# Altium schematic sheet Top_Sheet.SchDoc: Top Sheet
size A4; ApprovedBy: Watzek; CheckedBy: Watzek; Author: Watzek; DrawnBy: Watzek; Organization: HTL Hollabrunn; Address1: Abteilung Elektronik; Address2: Anton Ehrenfried-Straße 10; Address3: 2020 Hollabrunn; DocumentNumber: 01; Revision: 01; SheetNumber: 01; SheetTotal: 02; SPICEModelCacheIHPBHSPQ: <root> / <DocumentId>IHPBHSPQ</DocumentId> / <CacheFrame Number="0"> / <Model Name="cap" Kind="MDL"> / <Text>*Default semiconductor capacitor / .MODEL CAP C()</Text> / </Model> / </CacheFrame> / </root>
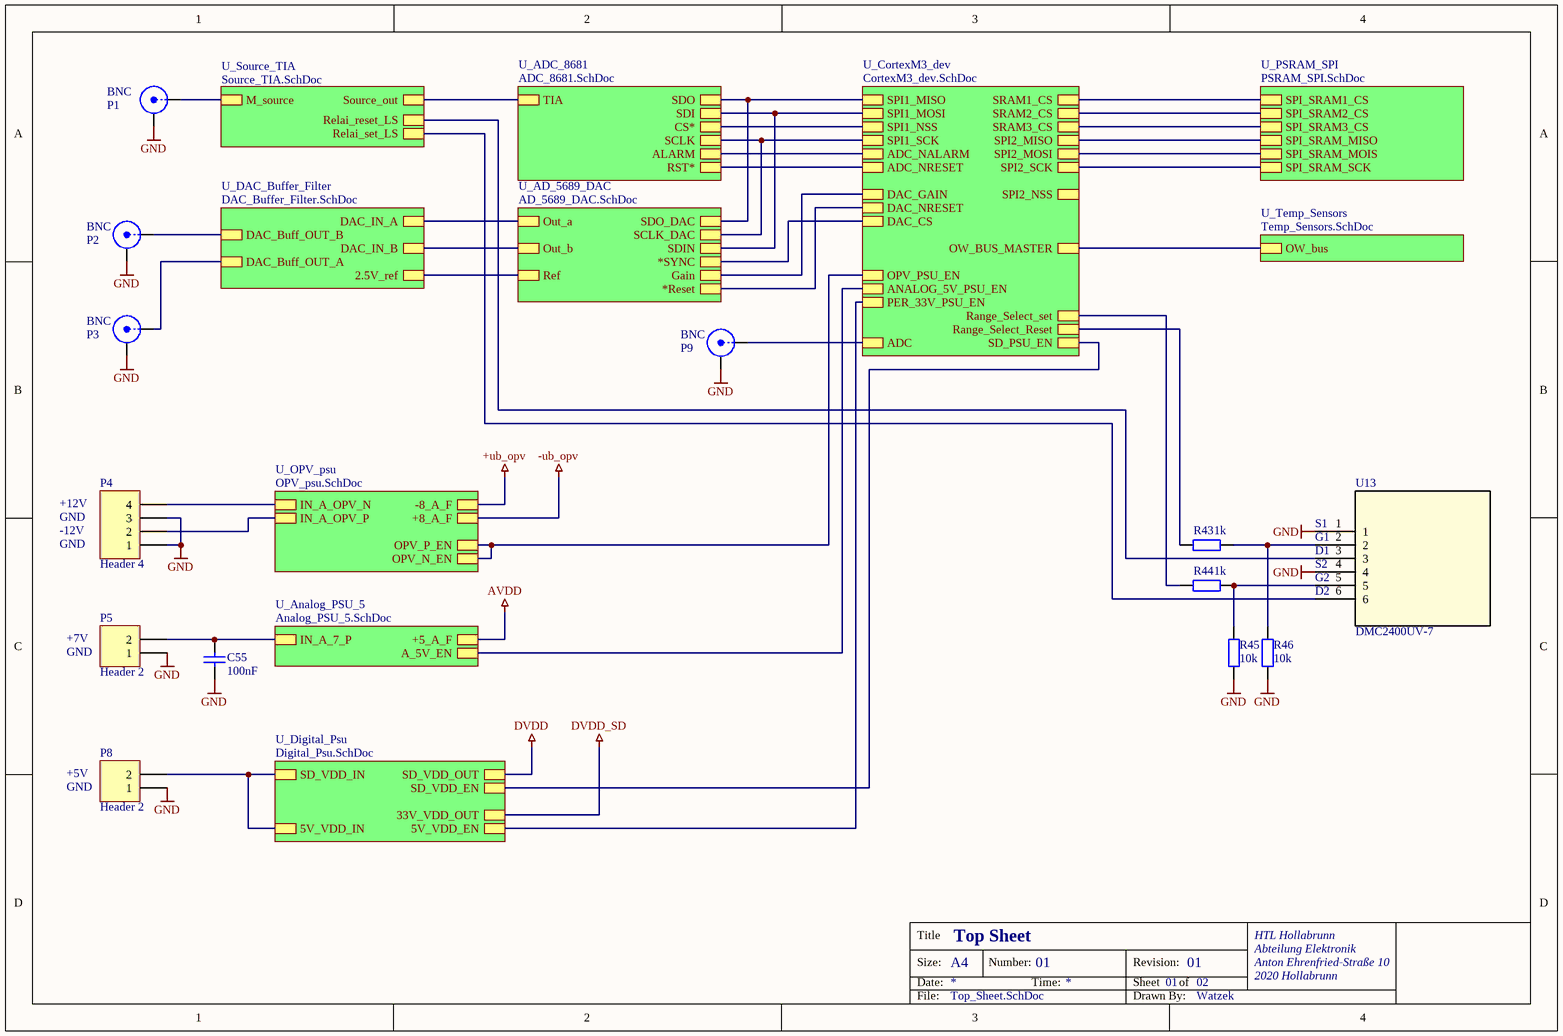
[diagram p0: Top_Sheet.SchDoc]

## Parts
C55  100nF  [C1206-KUE]
P1  BNC  [BNC_RA CON]
P2  BNC  [BNC_RA CON]
P3  BNC  [BNC_RA CON]
P4  Header 4  [HDR1X4]
P5  Header 2  [HDR1X2]
P8  Header 2  [HDR1X2]
P9  BNC  [BNC_RA CON]
R43  1k  [C1206-KUE]
R44  1k  [C1206-KUE]
R45  10k  [C1206-KUE]
R46  10k  [C1206-KUE]
U13  DMC2400UV-7  [SON_400UV-7_DIO]

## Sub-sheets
U_AD_5689_DAC = AD_5689_DAC.SchDoc: Ref, Out_a, Out_b, SDIN, SDO_DAC, SCLK_DAC, *SYNC, Gain, *Reset
U_ADC_8681 = ADC_8681.SchDoc: SDI, CS*, SCLK, SDO, ALARM, RST*, TIA
U_Analog_PSU_5 = Analog_PSU_5.SchDoc: IN_A_7_P, +5_A_F, A_5V_EN
U_CortexM3_dev = CortexM3_dev.SchDoc: SPI1_NSS, SPI1_SCK, SPI1_MISO, SPI1_MOSI, SPI2_NSS, SPI2_MISO, SPI2_MOSI, SPI2_SCK, ADC_NALARM, ADC_NRESET, DAC_GAIN, DAC_NRESET, SRAM1_CS, SRAM2_CS, SRAM3_CS, DAC_CS, OW_BUS_MASTER, OPV_PSU_EN, ANALOG_5V_PSU_EN, PER_33V_PSU_EN, SD_PSU_EN, Range_Select_set, Range_Select_Reset, ADC
U_DAC_Buffer_Filter = DAC_Buffer_Filter.SchDoc: DAC_IN_B, DAC_Buff_OUT_B, DAC_IN_A, 2.5V_ref, DAC_Buff_OUT_A
U_Digital_Psu = Digital_Psu.SchDoc: SD_VDD_IN, SD_VDD_OUT, SD_VDD_EN, 5V_VDD_IN, 33V_VDD_OUT, 5V_VDD_EN
U_OPV_psu = OPV_psu.SchDoc: IN_A_OPV_P, +8_A_F, IN_A_OPV_N, -8_A_F, OPV_P_EN, OPV_N_EN
U_PSRAM_SPI = PSRAM_SPI.SchDoc: SPI_SRAM_SCK, SPI_SRAM_MOIS, SPI_SRAM_MISO, SPI_SRAM1_CS, SPI_SRAM2_CS, SPI_SRAM3_CS
U_Source_TIA = Source_TIA.SchDoc: M_source, Source_out, Relai_set_LS, Relai_reset_LS
U_Temp_Sensors = Temp_Sensors.SchDoc: OW_bus

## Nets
GND: C55.1 P1.2(Y) P2.2(Y) P3.2(Y) P4.1 P4.3 P5.1 P8.1 P9.2(Y) R45.2 R46.2 U13.1 U13.4
NetC55_2: C55.2 P5.2 ; sheet U_Analog_PSU_5/IN_A_7_P
NetP1_1: P1.1(X) ; sheet U_Source_TIA/M_source
NetP2_1: P2.1(X) ; sheet U_DAC_Buffer_Filter/DAC_Buff_OUT_B
NetP3_1: P3.1(X) ; sheet U_DAC_Buffer_Filter/DAC_Buff_OUT_A
NetP4_2: P4.2 ; sheet U_OPV_psu/IN_A_OPV_P
NetP4_4: P4.4 ; sheet U_OPV_psu/IN_A_OPV_N
NetP8_2: P8.2 ; sheet U_Digital_Psu/SD_VDD_IN, sheet U_Digital_Psu/5V_VDD_IN
NetP9_1: P9.1(X) ; sheet U_CortexM3_dev/ADC
NetR43_1: R43.1 R46.1 U13.2
NetR43_2: R43.2 ; sheet U_CortexM3_dev/Range_Select_Reset
NetR44_1: R44.1 R45.1 U13.5
NetR44_2: R44.2 ; sheet U_CortexM3_dev/Range_Select_set
NetU13_3: U13.3 ; sheet U_Source_TIA/Relai_reset_LS
NetU13_6: U13.6 ; sheet U_Source_TIA/Relai_set_LS
(unnamed): sheet U_Source_TIA/Source_out, sheet U_ADC_8681/TIA
(unnamed): sheet U_PSRAM_SPI/SPI_SRAM_SCK, sheet U_CortexM3_dev/SPI2_SCK  [a separate net that carries the same name]
(unnamed): sheet U_PSRAM_SPI/SPI_SRAM_MOIS, sheet U_CortexM3_dev/SPI2_MOSI  [a separate net that carries the same name]
(unnamed): sheet U_PSRAM_SPI/SPI_SRAM_MISO, sheet U_CortexM3_dev/SPI2_MISO  [a separate net that carries the same name]
(unnamed): sheet U_PSRAM_SPI/SPI_SRAM1_CS, sheet U_CortexM3_dev/SRAM1_CS  [a separate net that carries the same name]
(unnamed): sheet U_PSRAM_SPI/SPI_SRAM2_CS, sheet U_CortexM3_dev/SRAM2_CS  [a separate net that carries the same name]
(unnamed): sheet U_PSRAM_SPI/SPI_SRAM3_CS, sheet U_CortexM3_dev/SRAM3_CS  [a separate net that carries the same name]
(unnamed): sheet U_DAC_Buffer_Filter/DAC_IN_B, sheet U_AD_5689_DAC/Out_b  [a separate net that carries the same name]
(unnamed): sheet U_DAC_Buffer_Filter/DAC_IN_A, sheet U_AD_5689_DAC/Out_a  [a separate net that carries the same name]
(unnamed): sheet U_DAC_Buffer_Filter/2.5V_ref, sheet U_AD_5689_DAC/Ref  [a separate net that carries the same name]
(unnamed): sheet U_ADC_8681/SDI, sheet U_AD_5689_DAC/SDIN, sheet U_CortexM3_dev/SPI1_MOSI  [a separate net that carries the same name]
(unnamed): sheet U_ADC_8681/CS*, sheet U_CortexM3_dev/SPI1_NSS  [a separate net that carries the same name]
(unnamed): sheet U_ADC_8681/SCLK, sheet U_AD_5689_DAC/SCLK_DAC, sheet U_CortexM3_dev/SPI1_SCK  [a separate net that carries the same name]
(unnamed): sheet U_ADC_8681/SDO, sheet U_AD_5689_DAC/SDO_DAC, sheet U_CortexM3_dev/SPI1_MISO  [a separate net that carries the same name]
(unnamed): sheet U_ADC_8681/ALARM, sheet U_CortexM3_dev/ADC_NALARM  [a separate net that carries the same name]
(unnamed): sheet U_ADC_8681/RST*, sheet U_CortexM3_dev/ADC_NRESET  [a separate net that carries the same name]
(unnamed): sheet U_AD_5689_DAC/*SYNC, sheet U_CortexM3_dev/DAC_CS  [a separate net that carries the same name]
(unnamed): sheet U_AD_5689_DAC/Gain, sheet U_CortexM3_dev/DAC_GAIN  [a separate net that carries the same name]
(unnamed): sheet U_AD_5689_DAC/*Reset, sheet U_CortexM3_dev/DAC_NRESET  [a separate net that carries the same name]
(unnamed): sheet U_Temp_Sensors/OW_bus, sheet U_CortexM3_dev/OW_BUS_MASTER  [a separate net that carries the same name]
(unnamed): sheet U_Digital_Psu/SD_VDD_EN, sheet U_CortexM3_dev/SD_PSU_EN  [a separate net that carries the same name]
(unnamed): sheet U_Digital_Psu/5V_VDD_EN, sheet U_CortexM3_dev/PER_33V_PSU_EN  [a separate net that carries the same name]
(unnamed): sheet U_Analog_PSU_5/A_5V_EN, sheet U_CortexM3_dev/ANALOG_5V_PSU_EN  [a separate net that carries the same name]
(unnamed): sheet U_OPV_psu/OPV_P_EN, sheet U_OPV_psu/OPV_N_EN, sheet U_CortexM3_dev/OPV_PSU_EN  [a separate net that carries the same name]

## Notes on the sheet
- +12V
- GND
- -12V
- (near U13) S1
- (near U13) G1
- (near U13) D1
- (near U13) S2
- (near U13) G2
- +7V
- (near U13) D2
- +5V

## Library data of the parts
C55 = Capacitor: Manufacturer: Kemet; Bezeichnung: Kerko +-10% 63V
P1-P3 P9 = BNC: BNC Elbow Connector
P4 = Header 4: Header, 4-Pin
P5 P8 = Header 2: Header, 2-Pin
R43-R46 = ResistorSMD: Resistor SMD; Manufacturer: AVX; Bezeichnung: SMD Wid. 1/8W 2%
U13 = DMC2400UV-7: Description; Manufacturer_Name: Diodes Inc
